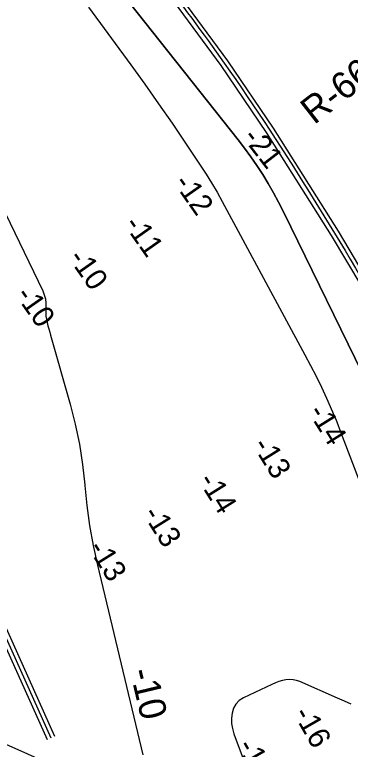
# Model space of a CAD drawing. Extents: x 3972907 to 3994831, y 172639 to 190852.
# Drawn here: x 3982172 to 3982691, y 185019 to 186154 of the extents above; entities that cross this region are included whole.
import ezdxf

# ---------------------------------------------------------------- set-up
doc = ezdxf.new("R2010")
doc.units = 0
for name, color, linetype in [('V-RIVR-JETY', 7, 'Continuous'), ('V-RIVR-RANG', 7, 'Continuous'), ('V-RIVR-RANG-IDEN', 7, 'Continuous'), ('V-TOPO-DPTH', 7, 'Continuous'), ('V-TOPO-MINR', 7, 'Continuous'), ('V-TOPO-MINR-IDEN', 7, 'Continuous')]:
    doc.layers.add(name, color=color, linetype=linetype)

msp = doc.modelspace()

# ---------------------------------------------------------------- linework, layer by layer
at = {"layer": 'V-RIVR-JETY'}
for points in [[(3981750.7, 187001.5), (3981876.1, 186854.6), (3982000.7, 186707.2), (3982147.3, 186531.2), (3982292.8, 186354.3), (3982399.4, 186220.8), (3982500.9, 186083.1), (3982571.4, 185978.9), (3982671.9, 185819.7), (3982768.2, 185657.9), (3982873.3, 185477.2), (3982976.5, 185295.5), (3983046.6, 185167.9), (3983116.7, 185040.5), (3983161.3, 184962.9), (3983205.5, 184884.8), (3983220.5, 184857.1), (3983235.4, 184829.3)], [(3981741.2, 186993.3), (3981866.5, 186846.6), (3981991.1, 186699.1), (3982137.7, 186523.3), (3982283.1, 186346.4), (3982389.5, 186213.2), (3982490.7, 186075.9), (3982560.9, 185972.1), (3982661.3, 185813.1), (3982757.5, 185651.5), (3982862.4, 185471), (3982965.6, 185289.4), (3983035.6, 185161.9), (3983105.8, 185034.4), (3983150.5, 184956.7), (3983194.6, 184878.8), (3983209.5, 184851.1), (3983224.4, 184823.4)], [(3981252.2, 186461.5), (3981989.5, 185490.7), (3982073.3, 185380.3), (3982227.7, 185036.8)], [(3981973.6, 185521.9), (3981994.4, 185494.5), (3982078.8, 185383.5), (3982233.4, 185039.3)], [(3981971.5, 185504), (3981984.5, 185486.9), (3982067.9, 185377.1), (3982222, 185034.2)]]:
    msp.add_lwpolyline(points, dxfattribs=at)
msp.add_spline([(3980663.7, 188142.5), (3980923.3, 187897.8), (3981219.1, 187593.7), (3981381.5, 187411.2), (3981548.8, 187223.5), (3981746, 186997.4), (3981995.9, 186703.1), (3982288, 186350.3), (3982495.8, 186079.5), (3982762.8, 185654.7), (3982971, 185292.4), (3983111.2, 185037.5), (3983200, 184881.8), (3983229.9, 184826.4)], degree=3, dxfattribs=at)
at = {"layer": 'V-RIVR-RANG'}
msp.add_lwpolyline([(3982021.3, 185087.7), (3990774.2, 181190.7)], dxfattribs=at)
at = {"layer": 'V-TOPO-DPTH'}
for points in [[(3982709.5, 185599.8), (3982587.4, 185849.6), (3982580, 185864.3), (3982572.2, 185878.8), (3982563.9, 185893.1), (3982555.4, 185907.2), (3982546.4, 185921), (3982537.1, 185934.6), (3982527.4, 185948), (3982517.4, 185961), (3982325.8, 186202.8)], [(3982049.8, 186070.1), (3982215.4, 185727.6), (3982217.8, 185721.4), (3982219.5, 185715.1), (3982220.3, 185708.6), (3982220.4, 185701.9), (3982220.2, 185698.7), (3982220.1, 185693.6), (3982220.3, 185688.5), (3982221.1, 185683.5), (3982222.2, 185678.5), (3982223.5, 185673.6), (3982224.8, 185668.6), (3982226.2, 185663.7), (3982227.6, 185658.8), (3982257.8, 185552.4), (3982265.5, 185521.6), (3982272.1, 185490.6), (3982276.8, 185459.3), (3982280.3, 185427.8), (3982280.3, 185426.6), (3982283.6, 185395.6), (3982287.8, 185364.7), (3982293.4, 185334), (3982299.9, 185303.5), (3982370.1, 185010.3)]]:
    msp.add_lwpolyline(points, dxfattribs=at)
at = {"layer": 'V-TOPO-MINR'}
for points in [[(3982325.8, 186202.8), (3982517.4, 185961), (3982527.4, 185948), (3982537.1, 185934.6), (3982546.4, 185921), (3982555.4, 185907.2), (3982563.9, 185893.1), (3982572.2, 185878.8), (3982580, 185864.3), (3982587.4, 185849.6), (3982709.5, 185599.8)], [(3982285.9, 186165.7), (3982351.5, 186076.5), (3982373.1, 186046.6), (3982394.5, 186016.6), (3982415.5, 185986.3), (3982436.2, 185955.7), (3982459, 185921.7), (3982467.9, 185907.9), (3982476.5, 185894.1), (3982484.8, 185879.9), (3982492.7, 185865.7), (3982620.8, 185628.8), (3982629.5, 185612.3), (3982638, 185595.6), (3982646.1, 185578.7), (3982653.9, 185561.7), (3982663.2, 185540.7), (3982666.1, 185534.1), (3982669, 185527.4), (3982671.7, 185520.7), (3982674.3, 185513.9), (3982799.8, 185185.3)], [(3982049.8, 186070.1), (3982215.4, 185727.6), (3982217.8, 185721.4), (3982219.5, 185715.1), (3982220.3, 185708.6), (3982220.4, 185701.9), (3982220.2, 185698.7), (3982220.1, 185693.6), (3982220.3, 185688.5), (3982221.1, 185683.5), (3982222.2, 185678.5), (3982223.5, 185673.6), (3982224.8, 185668.6), (3982226.2, 185663.7), (3982227.6, 185658.8), (3982257.8, 185552.4), (3982265.5, 185521.6), (3982272.1, 185490.6), (3982276.8, 185459.3), (3982280.3, 185427.8), (3982280.3, 185426.6), (3982283.6, 185395.6), (3982287.8, 185364.7), (3982293.4, 185334), (3982299.9, 185303.5), (3982370.1, 185010.3)], [(3982692.3, 185088.7), (3982681.7, 185093.2), (3982671, 185097.8), (3982613.1, 185123.6), (3982607.8, 185125.4), (3982602.4, 185126.5), (3982596.9, 185126.7), (3982591.4, 185126.3), (3982585.8, 185125.1), (3982580.3, 185123.6), (3982575, 185121.7), (3982569.7, 185119.4), (3982525.8, 185098.6), (3982519.3, 185094.2), (3982514, 185089), (3982510.4, 185082.4), (3982508, 185075), (3982507.3, 185066.9), (3982507.4, 185058.9), (3982508.8, 185050.9), (3982511, 185043.1), (3982538.9, 184967)]]:
    msp.add_lwpolyline(points, dxfattribs=at)

# ---------------------------------------------------------------- texts
at = {"layer": 'V-RIVR-RANG'}
for s, rotation, p in [('-21', 307.8283, (3982523.1, 185964.4)), ('-12', 305.1039, (3982416.9, 185894.1)), ('-11', 305.1039, (3982339.9, 185829.8)), ('-10', 305.1039, (3982253.8, 185778.3)), ('-10', 305.1039, (3982172.1, 185720.8)), ('-14', 301.9589, (3982624.6, 185540.3)), ('-13', 301.9589, (3982538.8, 185488.8)), ('-14', 301.9589, (3982454.9, 185434.4)), ('-13', 301.9589, (3982369.1, 185382.9)), ('-13', 301.9589, (3982284.5, 185330.1)), ('-16', 299.78, (3982602, 185074)), ('-16', 299.78, (3982515.2, 185024.3))]:
    msp.add_text(s, height=33.5, rotation=rotation, dxfattribs=at).set_placement(p)
at = {"layer": 'V-RIVR-RANG-IDEN'}
msp.add_text('R-664.0', height=41.5, rotation=37.9635, dxfattribs=at).set_placement((3982634.9, 185983.3))
at = {"layer": 'V-TOPO-MINR-IDEN'}
msp.add_text('-10', height=41.5, rotation=283.4617, dxfattribs=at).set_placement((3982349.8, 185139.8))

doc.saveas('drawing.dxf')
